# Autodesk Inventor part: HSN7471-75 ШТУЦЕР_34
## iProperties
Created: 2011-02
Part Number: HSN7471-75 ШТУЦЕР_34
Document SubType Name: Modeling
Designer: Чернышев Юрий
Mass: 21.3131 g
Surface Area: 86.9522 cm^2
Volume: 21.3131 cm^3
Density: 1 g/cm^3
Author: Чернышев Юрий
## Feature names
1. ExtrusionBlind1
2. ExtrusionBlind2
3. RevolutionAngle1
4. RevolutionAngle2
5. ExtrusionBlind3
6. ExtrusionBlind4
7. Hole1
8. Chamfer1
